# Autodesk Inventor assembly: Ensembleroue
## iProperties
Shininess: 21.0
Length Units: 11269
Angle Units: 11279
Time Units: 11290
Mass Units: 11283
Length Display Precision: 3
Angle Display Precision: 2
Compacted: True
Created: 2001-12
Part Number: Ensembleroue
Document SubType Name: Assemblage
Designer: pichon
Density: 0.0
Volumn: 0.0
Area: 0.0
PropertySet Name: Model Information
Control State: 0
Master: False
Checked Out: False
Author: pichon
